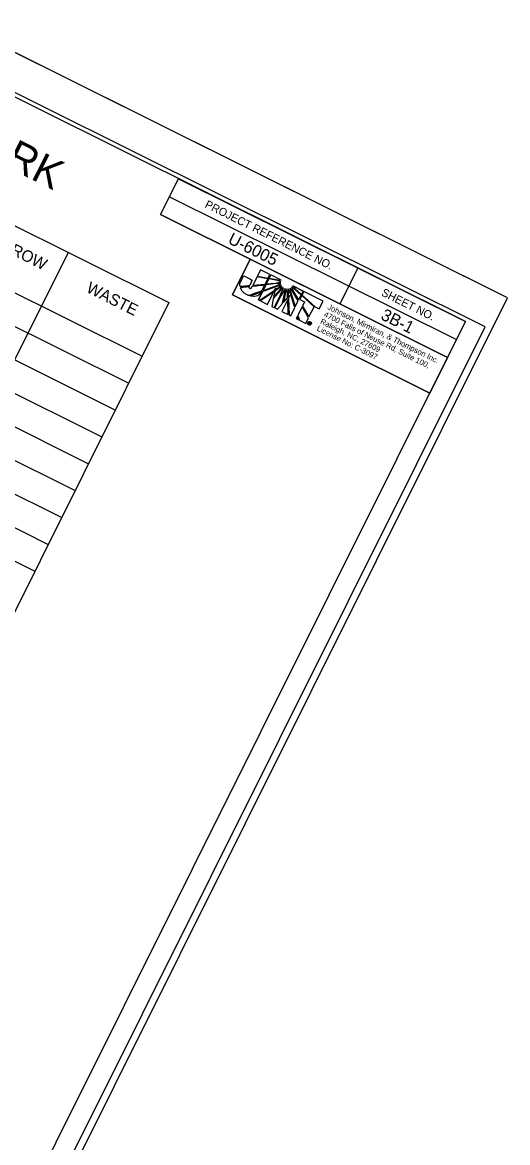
# Model space of a CAD drawing. Extents: x 1771109 to 1774678, y 884436 to 887277.
# Drawn here: x 1774376 to 1774678, y 885998 to 886698 of the extents above; entities that cross this region are included whole.
import ezdxf

# ---------------------------------------------------------------- set-up
doc = ezdxf.new("R2010")
doc.units = 0
for name, color, linetype in [('Default', 7, 'Continuous'), ('Prop PHM Black Shape', 7, 'Continuous'), ('Sheet Border Standard 30in CELL', 7, 'Continuous'), ('Sheet Cutting Line CELL', 7, 'Continuous'), ('Sheet Data Field CELL', 7, 'Continuous'), ('Sheet Plot Border Inside CELL', 7, 'Continuous'), ('Sheet Plot Border Outside CELL', 7, 'Continuous'), ('Sheet Summary Combination CELL', 7, 'Continuous'), ('Sheet Summary Combination Grid CELL', 7, 'Continuous'), ('Sheet Summary Earthwork CELL', 7, 'Continuous')]:
    doc.layers.add(name, color=color, linetype=linetype)

msp = doc.modelspace()

# ---------------------------------------------------------------- linework, layer by layer
at = {"layer": 'Default'}
for p, q in [((1774524.28, 886543.21), (1774522.38, 886539.39)), ((1774522.38, 886539.39), (1774528.94, 886538.12)), ((1774530.04, 886540.35), (1774524.28, 886543.21)), ((1774528.94, 886538.12), (1774530.04, 886540.35)), ((1774530.66, 886540.08), (1774529.63, 886538.01)), ((1774537.14, 886536.85), (1774530.66, 886540.08)), ((1774522.16, 886538.95), (1774519.49, 886533.58)), ((1774519.49, 886533.58), (1774527.07, 886534.36)), ((1774528.73, 886537.7), (1774522.16, 886538.95)), ((1774535.13, 886533.21), (1774525.52, 886529.74)), ((1774527.61, 886533.94), (1774525.82, 886530.35)), ((1774525.82, 886530.35), (1774535.04, 886533.65)), ((1774527.07, 886534.36), (1774528.73, 886537.7)), ((1774534.18, 886534.64), (1774527.61, 886533.94)), ((1774529.41, 886537.57), (1774527.86, 886534.45)), ((1774527.86, 886534.45), (1774533.55, 886535.03)), ((1774534.9, 886536.5), (1774529.41, 886537.57)), ((1774529.63, 886538.01), (1774535.12, 886536.94)), ((1774533.55, 886535.03), (1774536.9, 886535.79)), ((1774536.93, 886534.66), (1774534.18, 886534.64)), ((1774536.9, 886535.79), (1774534.9, 886536.5)), ((1774535.04, 886533.65), (1774536.93, 886534.66)), ((1774535.12, 886536.94), (1774537.14, 886536.85)), ((1774537.25, 886533.63), (1774535.13, 886533.21)), ((1774535.63, 886532.14), (1774537.25, 886533.63)), ((1774537.82, 886532.71), (1774535.95, 886531.81)), ((1774536.78, 886531.01), (1774537.82, 886532.71)), ((1774543.69, 886532.41), (1774545.12, 886529.23)), ((1774545.35, 886531.3), (1774543.69, 886532.41)), ((1774550.86, 886530), (1774544.48, 886533.2)), ((1774544.48, 886533.2), (1774545.72, 886531.64)), ((1774525.52, 886529.74), (1774522.92, 886524.51)), ((1774523.87, 886524.04), (1774532.81, 886530.21)), ((1774532.4, 886529.38), (1774524.32, 886523.81)), ((1774528.61, 886521.68), (1774532.4, 886529.38)), ((1774536.94, 886530.53), (1774532.22, 886525.1)), ((1774532.42, 886526), (1774536.78, 886531.01)), ((1774533.22, 886529.92), (1774532.42, 886526)), ((1774532.81, 886530.21), (1774533.56, 886531.73)), ((1774532.81, 886519.63), (1774536.63, 886527.31)), ((1774535.95, 886531.81), (1774533.22, 886529.92)), ((1774537.04, 886527.11), (1774533.22, 886519.42)), ((1774533.33, 886530.54), (1774535.63, 886532.14)), ((1774533.56, 886531.73), (1774533.33, 886530.54)), ((1774536.63, 886527.31), (1774538.64, 886531.98)), ((1774538.64, 886531.98), (1774536.94, 886530.53)), ((1774539.6, 886531.51), (1774537.04, 886527.11)), ((1774537.95, 886522.14), (1774539.44, 886529.28)), ((1774539.92, 886529.36), (1774538.52, 886522.8)), ((1774538.52, 886522.8), (1774541.18, 886525.84)), ((1774539.44, 886529.28), (1774539.6, 886531.51)), ((1774540.65, 886531.3), (1774539.92, 886529.36)), ((1774541.03, 886529.29), (1774540.65, 886531.3)), ((1774541.18, 886525.84), (1774541.03, 886529.29)), ((1774541.72, 886531.41), (1774541.51, 886529.22)), ((1774541.51, 886529.22), (1774541.6, 886526.31)), ((1774541.6, 886526.31), (1774542.46, 886527.3)), ((1774542.46, 886527.3), (1774541.63, 886525.62)), ((1774541.63, 886525.62), (1774542.08, 886514.98)), ((1774542.66, 886529.47), (1774541.72, 886531.41)), ((1774545.67, 886519.65), (1774542.66, 886529.47)), ((1774542.74, 886531.77), (1774543.06, 886529.63)), ((1774544.41, 886529.55), (1774542.74, 886531.77)), ((1774543.06, 886529.63), (1774545.97, 886520.25)), ((1774547.8, 886523.94), (1774544.41, 886529.55)), ((1774545.12, 886529.23), (1774548.06, 886524.45)), ((1774549.61, 886527.49), (1774545.35, 886531.3)), ((1774545.72, 886531.64), (1774549.83, 886527.93)), ((1774548.06, 886524.45), (1774549.61, 886527.49)), ((1774549.99, 886527.13), (1774548.84, 886524.81)), ((1774549.83, 886527.93), (1774550.86, 886530)), ((1774550.01, 886527.17), (1774549.99, 886527.13)), ((1774557.68, 886520.18), (1774550.01, 886527.17)), ((1774550.21, 886527.58), (1774550.18, 886527.51)), ((1774550.18, 886527.51), (1774558.39, 886520.1)), ((1774551.32, 886529.81), (1774550.21, 886527.58)), ((1774563.44, 886523.78), (1774551.32, 886529.81)), ((1774522.92, 886524.51), (1774523.87, 886524.04)), ((1774524.32, 886523.81), (1774528.61, 886521.68)), ((1774532.22, 886525.1), (1774531.23, 886520.41)), ((1774531.23, 886520.41), (1774532.81, 886519.63)), ((1774533.22, 886519.42), (1774534.82, 886518.63)), ((1774534.82, 886518.63), (1774537.95, 886522.14)), ((1774541.22, 886524.79), (1774537.49, 886517.3)), ((1774541.62, 886515.25), (1774541.22, 886524.79)), ((1774543.1, 886514.48), (1774545.67, 886519.65)), ((1774545.97, 886520.25), (1774547.8, 886523.94)), ((1774550.19, 886520.1), (1774547.62, 886514.94)), ((1774548.84, 886524.81), (1774551.8, 886523.34)), ((1774554.29, 886513.37), (1774550.19, 886520.1)), ((1774551.8, 886523.34), (1774550.42, 886520.57)), ((1774550.42, 886520.57), (1774554.51, 886513.82)), ((1774554.51, 886513.82), (1774557.68, 886520.18)), ((1774558.39, 886520.1), (1774560.97, 886518.82)), ((1774560.97, 886518.82), (1774563.44, 886523.78)), ((1774537.49, 886517.3), (1774541.62, 886515.25)), ((1774542.08, 886514.98), (1774543.1, 886514.48)), ((1774547.34, 886514.38), (1774546.54, 886512.77)), ((1774546.54, 886512.77), (1774548.03, 886512.02)), ((1774548.03, 886512.02), (1774547.34, 886514.38)), ((1774547.62, 886514.94), (1774548.61, 886511.74)), ((1774548.61, 886511.74), (1774552.51, 886509.8)), ((1774552.51, 886509.8), (1774554.29, 886513.37)), ((1774554.3, 886509.59), (1774554.74, 886510.47)), ((1774554.5, 886509.49), (1774554.3, 886509.59)), ((1774554.49, 886509.06), (1774554.4, 886508.87)), ((1774554.4, 886508.87), (1774554.49, 886509.06)), ((1774554.4, 886508.87), (1774554.4, 886508.87)), ((1774554.49, 886509.06), (1774554.5, 886509.06)), ((1774554.67, 886509.83), (1774554.5, 886509.49)), ((1774554.83, 886509.75), (1774554.67, 886509.83)), ((1774554.74, 886510.47), (1774555.1, 886510.29)), ((1774554.86, 886510.2), (1774554.75, 886509.99)), ((1774554.75, 886509.99), (1774554.91, 886509.91)), ((1774554.91, 886509.91), (1774554.83, 886509.75)), ((1774554.83, 886509.75), (1774554.91, 886509.91)), ((1774554.84, 886509.75), (1774554.83, 886509.75)), ((1774555.02, 886510.12), (1774554.86, 886510.2)), ((1774554.91, 886509.91), (1774554.92, 886509.91)), ((1774555.1, 886510.29), (1774555.02, 886510.12)), ((1774555.02, 886510.12), (1774555.1, 886510.29)), ((1774555.04, 886510.11), (1774555.02, 886510.12)), ((1774555.1, 886510.29), (1774555.16, 886510.26)), ((1774555.36, 886510.81), (1774555.27, 886510.63)), ((1774555.27, 886510.63), (1774555.36, 886510.81))]:
    msp.add_line(p, q, dxfattribs=at)
for points in [[(1774506.78, 886527.6), (1774629.87, 886466.28), (1774640.94, 886488.49), (1774517.85, 886549.82)], [(1774522.92, 886524.51), (1774525.52, 886529.74), (1774535.13, 886533.21), (1774537.25, 886533.63), (1774536.02, 886532.43), (1774533.33, 886530.54), (1774533.56, 886531.73), (1774532.81, 886530.21), (1774523.87, 886524.04)], [(1774544.48, 886533.2), (1774550.86, 886530), (1774549.83, 886527.93), (1774545.72, 886531.64)]]:
    msp.add_lwpolyline(points, close=True, dxfattribs=at)
for points in [[(1774522.38, 886539.39), (1774528.94, 886538.12), (1774530.04, 886540.35), (1774524.28, 886543.21), (1774522.38, 886539.39)], [(1774535.12, 886536.94), (1774537.14, 886536.85), (1774530.66, 886540.08), (1774529.63, 886538.01), (1774535.12, 886536.94)], [(1774519.49, 886533.58), (1774527.07, 886534.36), (1774528.73, 886537.7), (1774522.16, 886538.95), (1774519.49, 886533.58)], [(1774537.25, 886533.63), (1774535.13, 886533.21), (1774525.52, 886529.74), (1774522.92, 886524.51), (1774523.87, 886524.04), (1774532.81, 886530.21), (1774533.56, 886531.73), (1774533.33, 886530.54), (1774535.63, 886532.14), (1774537.25, 886533.63)], [(1774527.61, 886533.94), (1774525.82, 886530.35), (1774535.04, 886533.65), (1774536.93, 886534.66), (1774534.18, 886534.64), (1774527.61, 886533.94)], [(1774529.41, 886537.57), (1774527.86, 886534.45), (1774533.55, 886535.03), (1774536.9, 886535.79), (1774534.9, 886536.5), (1774529.41, 886537.57)], [(1774537.82, 886532.71), (1774535.95, 886531.81), (1774533.22, 886529.92), (1774532.42, 886526), (1774536.78, 886531.01), (1774537.82, 886532.71)], [(1774543.69, 886532.41), (1774545.12, 886529.23), (1774548.06, 886524.45), (1774549.61, 886527.49), (1774545.35, 886531.3), (1774543.69, 886532.41)], [(1774545.72, 886531.64), (1774549.83, 886527.93), (1774550.86, 886530), (1774544.48, 886533.2), (1774545.72, 886531.64)], [(1774524.32, 886523.81), (1774528.61, 886521.68), (1774532.4, 886529.38), (1774524.32, 886523.81)], [(1774536.94, 886530.53), (1774532.22, 886525.1), (1774531.23, 886520.41), (1774532.81, 886519.63), (1774536.63, 886527.31), (1774538.64, 886531.98), (1774536.94, 886530.53)], [(1774539.6, 886531.51), (1774537.04, 886527.11), (1774533.22, 886519.42), (1774534.82, 886518.63), (1774537.95, 886522.14), (1774539.44, 886529.28), (1774539.6, 886531.51)], [(1774540.65, 886531.3), (1774539.92, 886529.36), (1774538.52, 886522.8), (1774541.18, 886525.84), (1774541.03, 886529.29), (1774540.65, 886531.3)], [(1774541.72, 886531.41), (1774541.51, 886529.22), (1774541.6, 886526.31), (1774542.46, 886527.3), (1774541.63, 886525.62), (1774542.08, 886514.98), (1774543.1, 886514.48), (1774545.67, 886519.65), (1774542.66, 886529.47), (1774541.72, 886531.41)], [(1774542.74, 886531.77), (1774543.06, 886529.63), (1774545.97, 886520.25), (1774547.8, 886523.94), (1774544.41, 886529.55), (1774542.74, 886531.77)], [(1774550.01, 886527.17), (1774549.99, 886527.13), (1774548.84, 886524.81), (1774551.8, 886523.34), (1774550.42, 886520.57), (1774554.51, 886513.82), (1774557.68, 886520.18), (1774550.01, 886527.17)], [(1774563.44, 886523.78), (1774551.32, 886529.81), (1774550.21, 886527.58), (1774550.18, 886527.51), (1774558.39, 886520.1), (1774560.97, 886518.82), (1774563.44, 886523.78)], [(1774537.49, 886517.3), (1774541.62, 886515.25), (1774541.22, 886524.79), (1774537.49, 886517.3)], [(1774550.19, 886520.1), (1774547.62, 886514.94), (1774548.61, 886511.74), (1774552.51, 886509.8), (1774554.29, 886513.37), (1774550.19, 886520.1), (1774550.19, 886520.1)], [(1774546.54, 886512.77), (1774546.54, 886512.77), (1774548.03, 886512.02), (1774547.34, 886514.38), (1774546.54, 886512.77)], [(1774555.15, 886509.43), (1774555.13, 886509.38), (1774555.12, 886509.34), (1774555.1, 886509.31), (1774555.08, 886509.2), (1774554.89, 886509.29)]]:
    msp.add_lwpolyline(points, dxfattribs=at)
for points, degree in [([(1774519.06, 886536.87), (1774519.06, 886536.87), (1774513.73, 886539.52), (1774513.73, 886539.52), (1774513.73, 886539.52), (1774512.07, 886536.18), (1774512.07, 886536.18), (1774512.07, 886536.18), (1774511.9, 886535.83), (1774511.9, 886535.83), (1774511.38, 886534.79), (1774511.31, 886533.79), (1774511.57, 886532.79), (1774511.57, 886532.79), (1774517.28, 886533.28), (1774517.31, 886533.34), (1774517.31, 886533.34), (1774519.06, 886536.87), (1774519.06, 886536.87)], 3), ([(1774517.5, 886531.66), (1774517.16, 886531.83), (1774516.96, 886532.16), (1774517.16, 886532.86), (1774517.16, 886532.86), (1774511.75, 886532.36), (1774511.75, 886532.36), (1774512.35, 886530.39), (1774513.99, 886528.58), (1774515.71, 886527.72), (1774516.16, 886527.5), (1774516.52, 886527.37), (1774517.05, 886527.22), (1774517.05, 886527.22), (1774524.9, 886530.01), (1774524.9, 886530.01), (1774524.9, 886530.01), (1774526.83, 886533.89), (1774526.83, 886533.89), (1774526.83, 886533.89), (1774519.25, 886533.09), (1774519.25, 886533.09), (1774518.53, 886531.64), (1774517.98, 886531.42), (1774517.5, 886531.66)], 3), ([(1774517.5, 886531.66), (1774517.16, 886531.83), (1774516.96, 886532.16), (1774517.16, 886532.86), (1774517.16, 886532.86), (1774511.75, 886532.36), (1774511.75, 886532.36), (1774512.35, 886530.39), (1774513.99, 886528.58), (1774515.71, 886527.72), (1774516.16, 886527.5), (1774516.52, 886527.37), (1774517.05, 886527.22), (1774517.05, 886527.22), (1774524.9, 886530.01), (1774524.9, 886530.01), (1774524.9, 886530.01), (1774526.83, 886533.89), (1774526.83, 886533.89), (1774526.83, 886533.89), (1774519.25, 886533.09), (1774519.25, 886533.09), (1774518.53, 886531.64), (1774517.98, 886531.42), (1774517.5, 886531.66)], 3), ([(1774524.6, 886529.4), (1774524.6, 886529.4), (1774517.81, 886527), (1774517.81, 886527), (1774520.28, 886526.45), (1774523.19, 886526.82), (1774524.6, 886529.4)], 3), ([(1774554.4, 886508.87), (1774554.13, 886509), (1774553.95, 886509.22), (1774553.85, 886509.5), (1774553.75, 886509.78), (1774553.77, 886510.06), (1774553.9, 886510.34), (1774554.04, 886510.61), (1774554.25, 886510.79), (1774554.53, 886510.87), (1774554.81, 886510.96), (1774555.09, 886510.95), (1774555.36, 886510.81)], 3), ([(1774555.27, 886510.63), (1774555.05, 886510.73), (1774554.83, 886510.75), (1774554.61, 886510.68), (1774554.38, 886510.61), (1774554.2, 886510.46), (1774554.1, 886510.24), (1774553.99, 886510.02), (1774553.97, 886509.79), (1774554.05, 886509.56), (1774554.13, 886509.34), (1774554.27, 886509.17), (1774554.49, 886509.06)], 3), ([(1774555.87, 886509.36), (1774555.73, 886509.09), (1774555.52, 886508.9), (1774555.24, 886508.8), (1774554.96, 886508.71), (1774554.68, 886508.73), (1774554.4, 886508.87)], 3), ([(1774554.5, 886509.06), (1774554.72, 886508.95), (1774554.94, 886508.93), (1774555.16, 886509.01), (1774555.39, 886509.09), (1774555.57, 886509.24), (1774555.67, 886509.46), (1774555.78, 886509.67), (1774555.8, 886509.9), (1774555.72, 886510.13), (1774555.64, 886510.35), (1774555.49, 886510.52), (1774555.27, 886510.63)], 3), ([(1774554.98, 886509.64), (1774554.96, 886509.67), (1774554.92, 886509.71), (1774554.84, 886509.75)], 2), ([(1774554.89, 886509.29), (1774554.89, 886509.35), (1774554.9, 886509.41), (1774554.93, 886509.47), (1774554.97, 886509.55), (1774554.99, 886509.61), (1774554.98, 886509.64)], 3), ([(1774554.92, 886509.91), (1774555.05, 886509.85), (1774555.13, 886509.85), (1774555.17, 886509.93), (1774555.2, 886509.99), (1774555.16, 886510.05), (1774555.04, 886510.11)], 3), ([(1774555.16, 886509.69), (1774555.2, 886509.63), (1774555.2, 886509.54), (1774555.15, 886509.43)], 2), ([(1774555.16, 886510.26), (1774555.38, 886510.15), (1774555.45, 886510.01), (1774555.36, 886509.83), (1774555.32, 886509.75), (1774555.26, 886509.7), (1774555.16, 886509.69)], 3), ([(1774555.36, 886510.81), (1774555.63, 886510.68), (1774555.82, 886510.46), (1774555.92, 886510.18), (1774556.02, 886509.91), (1774556, 886509.63), (1774555.87, 886509.36)], 3)]:
    msp.add_open_spline(points, degree=degree, dxfattribs=at)
at = {"layer": 'Prop PHM Black Shape'}
msp.add_lwpolyline([(1774517.84, 886549.82), (1774640.94, 886488.5), (1774629.87, 886466.28), (1774506.77, 886527.59)], close=True, dxfattribs=at)
at = {"layer": 'Sheet Border Standard 30in CELL'}
for p, q in [((1774467.49, 886588.96), (1774646.52, 886499.69)), ((1774461.91, 886577.77), (1774640.94, 886488.5)), ((1774461.91, 886577.77), (1774640.94, 886488.5)), ((1774584.98, 886544.34), (1774573.83, 886521.97))]:
    msp.add_line(p, q, dxfattribs=at)
for points in [[(1774652.12, 886510.92), (1773309.73, 887180.24), (1772841.21, 886240.56), (1774183.6, 885571.25)], [(1774473.09, 886600.19), (1774652.12, 886510.92), (1774640.94, 886488.5), (1774461.91, 886577.77)]]:
    msp.add_lwpolyline(points, close=True, dxfattribs=at)
at = {"layer": 'Sheet Cutting Line CELL'}
msp.add_line((1774678.49, 886525.71), (1773171.43, 887277.13), dxfattribs=at)
at = {"layer": 'Sheet Plot Border Inside CELL'}
msp.add_lwpolyline([(1774664.45, 886507.63), (1773173.05, 887251.23), (1772702.25, 886307), (1774193.65, 885563.39)], close=True, dxfattribs=at)
at = {"layer": 'Sheet Plot Border Outside CELL'}
msp.add_lwpolyline([(1774678.49, 886525.71), (1773171.43, 887277.13), (1772680.6, 886292.7), (1774187.66, 885541.29)], close=True, dxfattribs=at)
at = {"layer": 'Sheet Summary Combination Grid CELL'}
for p, q in [((1774016.48, 886747.48), (1774467.11, 886522.79)), ((1773999.74, 886713.92), (1774450.38, 886489.23)), ((1773991.38, 886697.14), (1774442.01, 886472.45)), ((1773983.01, 886680.36), (1774433.65, 886455.67)), ((1773974.64, 886663.58), (1774425.28, 886438.89)), ((1773966.28, 886646.8), (1774416.91, 886422.11)), ((1773957.91, 886630.02), (1774408.55, 886405.33)), ((1773949.54, 886613.24), (1774400.18, 886388.55)), ((1773941.18, 886596.46), (1774391.81, 886371.77)), ((1773932.81, 886579.68), (1774383.45, 886354.99)), ((1774404.15, 886554.18), (1774144.79, 886034.01)), ((1774467.11, 886522.79), (1774207.75, 886002.62))]:
    msp.add_line(p, q, dxfattribs=at)

# ---------------------------------------------------------------- texts
at = {"layer": 'Default'}
for s, height, p in [('Johnson, Mirmiran, & Thompson Inc.', 3.5139, (1774565.7, 886518.87)), ('Raleigh, NC, 27609', 3.4135, (1774561.23, 886509.89)), ('4700 Falls of Neuse Rd, Suite 100, ', 3.4135, (1774563.41, 886514.26)), ('License No: C-3097', 3.4135, (1774559.06, 886505.53))]:
    msp.add_text(s, height=height, rotation=333.518, dxfattribs=at).set_placement(p)
at = {"layer": 'Sheet Border Standard 30in CELL'}
for s, height, p in [('PROJECT REFERENCE NO.', 5.0001, (1774489.08, 886582.49)), ('SHEET NO.', 5, (1774599.24, 886527.45))]:
    msp.add_text(s, height=height, rotation=333.49928, dxfattribs=at).set_placement(p)
at = {"layer": 'Sheet Data Field CELL'}
for s, p in [('U-6005', (1774503.36, 886560.18)), ('3B-1', (1774598.81, 886512.64))]:
    msp.add_text(s, height=7.5, rotation=333.49928, dxfattribs=at).set_placement(p)
at = {"layer": 'Sheet Summary Combination CELL'}
for s, p in [('BORROW', (1774349.02, 886562.82)), ('WASTE', (1774414.94, 886529.68))]:
    msp.add_text(s, height=7.2, rotation=333.30813, dxfattribs=at).set_placement(p)
at = {"layer": 'Sheet Summary Earthwork CELL'}
msp.add_text('SUMMARY OF EARTHWORK', height=18.7499, rotation=333.30813, dxfattribs=at).set_placement((1774091.42, 886745.48))

doc.saveas('drawing.dxf')
